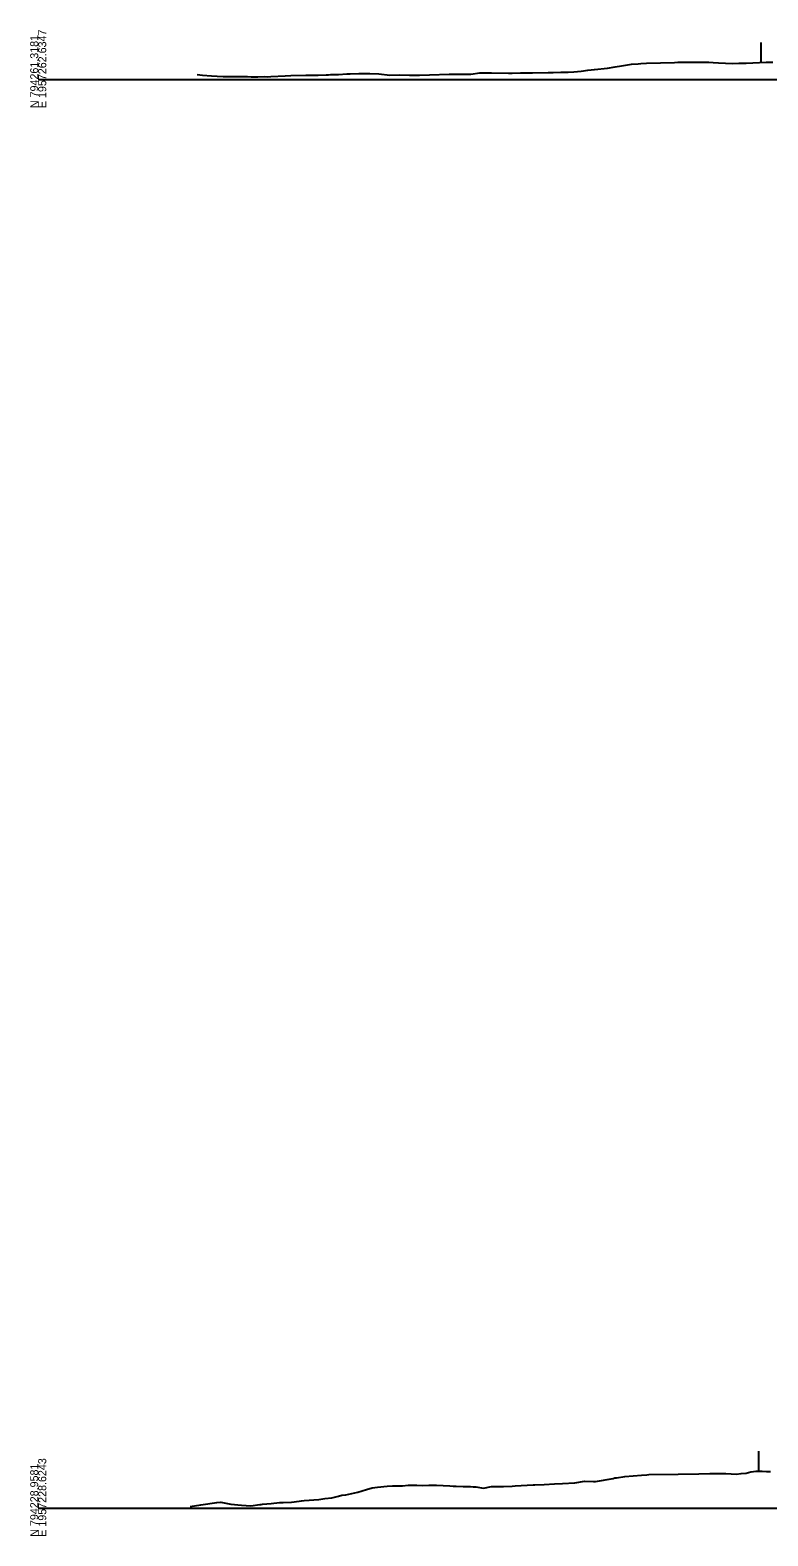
# Model space of a CAD drawing. Extents: x -4026 to 9638, y -10 to 19609.
# Drawn here: x -3003 to -2745, y 9990 to 10517 of the extents above; entities that cross this region are included whole.
import ezdxf

# ---------------------------------------------------------------- set-up
doc = ezdxf.new("R2010")
doc.units = 0
for name, color, linetype in [('Default', 7, 'Continuous'), ('RD_EX_Fence_Other', 7, 'Continuous'), ('RD_GPK_XS_Cell', 7, 'Continuous'), ('RD_XS_ExGround', 7, 'Continuous')]:
    doc.layers.add(name, color=color, linetype=linetype)

msp = doc.modelspace()

# ---------------------------------------------------------------- linework, layer by layer
at = {"layer": 'RD_EX_Fence_Other'}
for p, q in [((-2747.15, 10513), (-2747.15, 10506)), ((-2747.92, 10019.97), (-2747.92, 10012.97))]:
    msp.add_line(p, q, dxfattribs=at)
at = {"layer": 'RD_GPK_XS_Cell'}
for p, q in [((-3000, 10500), (-2650, 10500)), ((-3000, 10000), (-2650, 10000))]:
    msp.add_line(p, q, dxfattribs=at)
at = {"layer": 'RD_XS_ExGround'}
for points in [[(-2944.42, 10501.73), (-2942.5, 10501.56), (-2939.33, 10501.28), (-2937.35, 10501.15), (-2935.28, 10501.09), (-2933.81, 10501.05), (-2932.4, 10501.01), (-2930.28, 10501.02), (-2928.06, 10501.01), (-2926.74, 10501.01), (-2925.47, 10501), (-2923.2, 10500.98), (-2920.84, 10501.01), (-2919.67, 10501), (-2918.54, 10501.06), (-2913.62, 10501.32), (-2911.61, 10501.42), (-2906.4, 10501.57), (-2905.52, 10501.58), (-2904.68, 10501.58), (-2901.99, 10501.56), (-2899.18, 10501.67), (-2898.45, 10501.68), (-2897.75, 10501.71), (-2894.91, 10501.81), (-2891.96, 10501.98), (-2891.38, 10502.01), (-2890.82, 10502.02), (-2887.84, 10502.11), (-2884.74, 10502.12), (-2884.3, 10502.1), (-2883.89, 10502.08), (-2880.77, 10502), (-2876.96, 10501.55), (-2873.7, 10501.67), (-2870.03, 10501.48), (-2866.62, 10501.54), (-2863.08, 10501.68), (-2856.17, 10501.91), (-2855.85, 10501.9), (-2852.48, 10501.88), (-2848.94, 10501.88), (-2848.63, 10501.91), (-2845.41, 10502.33), (-2842.31, 10502.37), (-2841.87, 10502.37), (-2841.41, 10502.37), (-2835.38, 10502.27), (-2834.8, 10502.26), (-2834.19, 10502.26), (-2831.26, 10502.37), (-2828.45, 10502.33), (-2827.72, 10502.33), (-2826.97, 10502.36), (-2821.52, 10502.44), (-2820.65, 10502.42), (-2819.75, 10502.47), (-2817.12, 10502.55), (-2814.58, 10502.62), (-2812.53, 10502.68), (-2810.04, 10502.92), (-2807.65, 10503.23), (-2806.51, 10503.37), (-2805.31, 10503.52), (-2800.72, 10504.02), (-2798.09, 10504.43), (-2795.9, 10504.76), (-2793.79, 10505.13), (-2792.36, 10505.39), (-2790.08, 10505.53), (-2789.08, 10505.65), (-2787.16, 10505.78), (-2777.3, 10506.01), (-2776.2, 10506.04), (-2774.38, 10506.05), (-2765.26, 10506.11), (-2763.78, 10506.02), (-2761.95, 10505.9), (-2757, 10505.62), (-2754.77, 10505.68), (-2753.46, 10505.7), (-2752.21, 10505.74), (-2747.55, 10505.99), (-2745.28, 10506.07), (-2742.85, 10506.04)], [(-2946.78, 10000.58), (-2943.08, 10001.18), (-2937.51, 10001.96), (-2936.13, 10002.14), (-2932.63, 10001.36), (-2928.84, 10001.09), (-2925.56, 10000.86), (-2922.46, 10001.28), (-2922.02, 10001.34), (-2921.55, 10001.38), (-2918.48, 10001.67), (-2915.59, 10001.97), (-2914.95, 10002.04), (-2914.27, 10002.02), (-2911.41, 10002.07), (-2908.71, 10002.41), (-2907.87, 10002.54), (-2906.98, 10002.64), (-2901.84, 10003.09), (-2899.69, 10003.35), (-2897.26, 10003.63), (-2894.97, 10004.23), (-2893.72, 10004.5), (-2892.4, 10004.7), (-2890.19, 10005.09), (-2888.09, 10005.59), (-2886.65, 10006.05), (-2885.12, 10006.58), (-2883.11, 10007.18), (-2881.22, 10007.41), (-2877.83, 10007.76), (-2876.04, 10007.81), (-2874.35, 10007.82), (-2872.5, 10007.87), (-2870.54, 10008), (-2868.96, 10008.06), (-2867.47, 10008.06), (-2865.43, 10007.99), (-2863.26, 10008), (-2860.6, 10008.01), (-2855.97, 10007.82), (-2854.82, 10007.73), (-2853.73, 10007.67), (-2851.28, 10007.55), (-2848.68, 10007.55), (-2847.74, 10007.49), (-2846.85, 10007.47), (-2844.2, 10007.02), (-2841.39, 10007.55), (-2840.67, 10007.59), (-2839.98, 10007.63), (-2837.13, 10007.63), (-2834.11, 10007.75), (-2833.11, 10007.79), (-2826.82, 10008.17), (-2826.24, 10008.2), (-2822.98, 10008.26), (-2819.36, 10008.5), (-2816.52, 10008.62), (-2812.25, 10008.83), (-2808.83, 10009.45), (-2805.62, 10009.31), (-2804.96, 10009.3), (-2798.74, 10010.42), (-2798.22, 10010.57), (-2797.67, 10010.64), (-2794.69, 10011.08), (-2788.89, 10011.57), (-2787, 10011.72), (-2786.3, 10011.74), (-2776.04, 10011.96), (-2768.85, 10012.06), (-2764.96, 10012.12), (-2763.46, 10012.13), (-2762.27, 10012.16), (-2759.32, 10012.18), (-2757.5, 10012.05), (-2755.78, 10011.86), (-2753.95, 10012.1), (-2752.24, 10012.3), (-2750.63, 10012.69), (-2748.7, 10012.98), (-2746.66, 10012.96), (-2745.17, 10012.82), (-2743.76, 10012.83)]]:
    msp.add_lwpolyline(points, dxfattribs=at)

# ---------------------------------------------------------------- texts
at = {"layer": 'Default'}
for p in [(-3000, 10500), (-3000, 10000)]:
    msp.add_text('-', height=0.0001, dxfattribs=at).set_placement(p)
at = {"layer": 'RD_GPK_XS_Cell'}
for s, p in [('N 794261.3181', (-3000, 10490)), ('E 1957262.6347', (-2997.2, 10490)), ('N 794228.9581', (-3000, 9990)), ('E 1957228.6243', (-2997.2, 9990))]:
    msp.add_text(s, height=2.8, rotation=90, dxfattribs=at).set_placement(p)

doc.saveas('drawing.dxf')
